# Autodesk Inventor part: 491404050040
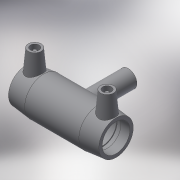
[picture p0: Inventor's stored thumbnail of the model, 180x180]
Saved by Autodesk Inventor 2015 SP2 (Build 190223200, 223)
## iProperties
Created: 2017-06
Part Number: 491404050040
Material: Generic
Description: PLASSON REDUCING TEE 50x40x50
Document SubType Name: Modeling
Designer: KIM
Mass: 57.3761 g
Surface Area: 241.06 cm^2
Volume: 57.3761 cm^3
Density: 1 g/cm^3
Appearance: Default
Author: KIM
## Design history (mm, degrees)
derived "491404.ipt"
feature "Solid1::491404.ipt"
tag "TaggingFeature1"
body "Solid1"
other parameters: "d0" = 139, "d2" = 68, "d3" = 48, "d4" = 27.8, "d5" = 61.2, "d6" = 47.5, "d8" = 168 deg, "d10" = 19.2, "d11" = 6.4, "d13" = 139, "d14" = 17.6296, "d17" = 45, "d19" = 3.52592, "d20" = 168 deg, "d22" = 63.24, "d23" = 68, "d25" = 135 deg, "d26" = 97.3, "d29" = 52, "d30" = 15, "d31" = 55.6, "d34" = 5 deg, "d35" = 15, "d39" = 5 deg, "d41" = 4, "d42" = 14, "d43" = 0, "d45" = 4, "d46" = 6, "d47" = 0, "d51" = 0, "d52" = 32, "d54" = 0, "d55" = 61.2, "d56" = 68, "d57" = 48.65, "d58" = 135 deg, "d59" = 48, "d60" = 48, "d61" = 135 deg, "d72" = 63.245, "d73" = 31.6225, "d75" = 42, "d77" = 0, "d78" = 32, "d80" = 0, "d82" = 56, "d83" = 0, "d84" = 3, "d85" = 0, "d86" = 16, "d87" = 61.9752, "d88" = 6.4, "d89" = 3, "d90" = 0, "L_" = 139, "L_1" = 48, "D_" = 68, "A_" = 52, "d_2" = 12
